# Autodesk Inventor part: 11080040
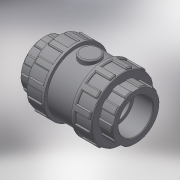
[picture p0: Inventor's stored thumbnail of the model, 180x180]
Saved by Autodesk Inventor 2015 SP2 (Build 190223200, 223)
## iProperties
Created: 2017-11
Part Number: 11080040
Material: Generic
Description: PLASSON CHECK VALVE CEM 40 PTFE COATED SPRING + EPDM O-RING
Document SubType Name: Modeling
Designer: KIM
Density: 1 g/cm^3
Appearance: Default
Author: KIM
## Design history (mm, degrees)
derived "110800 - 110600 110900-110000.ipt"
feature "Solid1::110800 - 110600 110900-110000.ipt"
tag "TaggingFeature1"
body "Solid1"
other parameters: "d3" = 26, "d4" = 32, "d5" = 18.2, "d7" = 56, "d8" = 72, "d13" = 1.2, "d23" = 26, "d24" = 76.8, "d25" = 0.8, "d26" = 1.2, "d27" = 12, "d28" = 6, "d29" = 19.5, "d30" = 0, "d35" = 1.2, "d45" = 360 deg, "d47" = 0.8, "d51" = 24, "d53" = 0, "d54" = 1.6, "d55" = 8, "d56" = 4, "d57" = 18.2, "d58" = 0, "d59" = 1.2, "d61" = 360 deg, "l_" = 26
